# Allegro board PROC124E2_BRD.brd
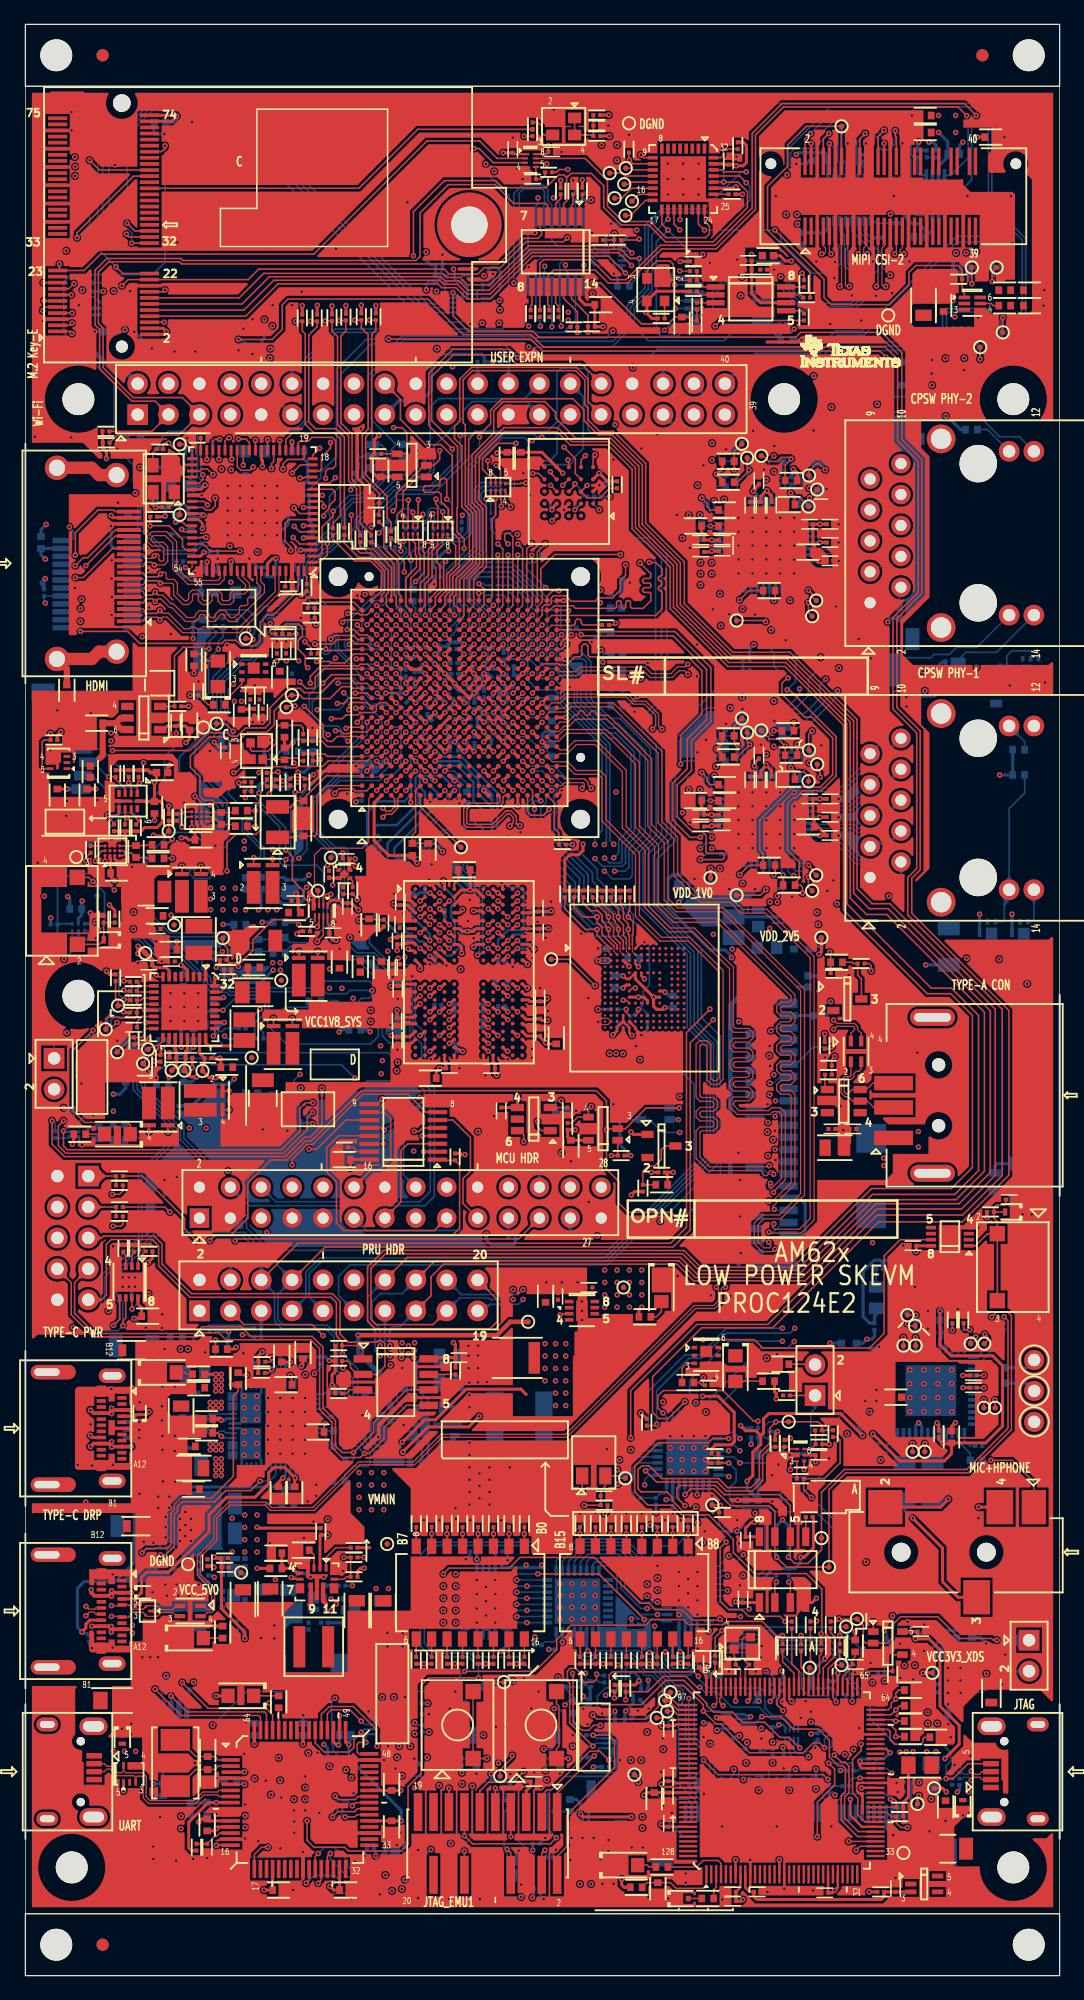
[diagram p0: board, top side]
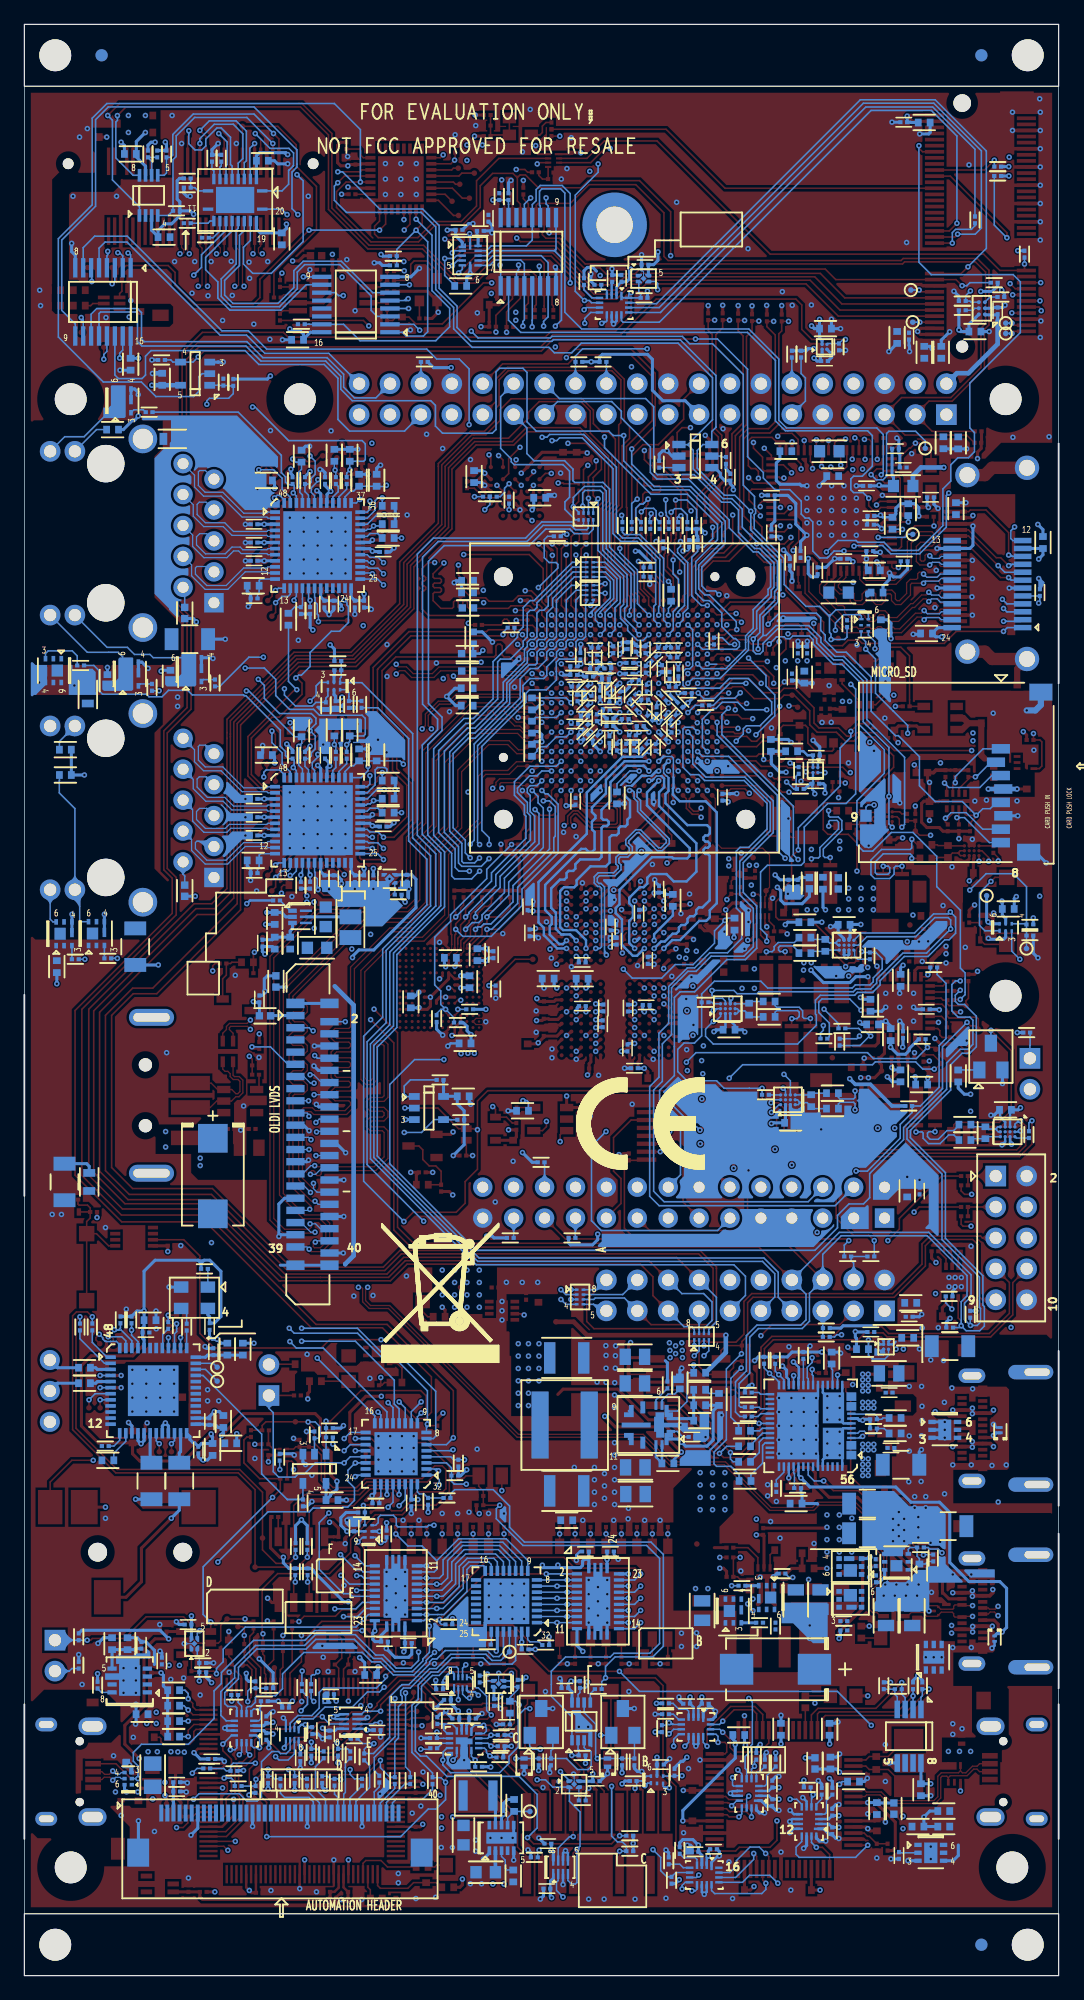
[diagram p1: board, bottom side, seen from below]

Outline 85 x 160.26 mm; copper layers: TOP, L02GND01, L03_SIG1, L04_PWR01, L05_PWR02, L06_SIG2, L07_GND02, BOTTOM. Coordinates in mm from the lower left corner of the outline.
Outline path: rectangle 0,155.18 85,160.26 ; rectangle 0,0 85,5.08 ; 0,155.18 0,5.08 85,5.08 85,155.18 0,155.18

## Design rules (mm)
net group COM_SDIO_CMD: nets COM_SDIO_CMD MMC2_CMD
net group COM_SDIO_D0: nets COM_SDIO_D0 MMC2_D0
net group COM_SDIO_D1: nets COM_SDIO_D1 MMC2_D1
net group COM_SDIO_D2: nets COM_SDIO_D2 MMC2_D2
net group COM_SDIO_D3: nets COM_SDIO_D3 MMC2_D3
net group CPSW_ETH1_D0: nets CPSW_ETH1_D0N CPSW_ETH1_D0P
net group CPSW_ETH1_D1: nets CPSW_ETH1_D1M CPSW_ETH1_D1P
net group CPSW_ETH1_D2: nets CPSW_ETH1_D2M CPSW_ETH1_D2P
net group CPSW_ETH1_D3: nets CPSW_ETH1_D3M CPSW_ETH1_D3P
net group CPSW_RGMII1_RXC: nets CPSW_RGMII1_RXC N17167245
net group CPSW_RGMII1_TXC: nets CPSW_RGMII1_TXC CPSW_RGMII_TXC_R
net group CPSW_RGMII2_RXC: nets CPSW_RGMII2_RXC N22623025
net group CPSW_RGMII2_TXC: nets CPSW_RGMII2_TXC CPSW_RGMII2_TXC_R
net group DDR_ADDRESS: nets LPDDR4_CK_N LPDDR4_CK_P
net group HDMI_PCLK: nets HDMI_PCLK SOC_VOUT0_PCLK
net group MMC2_CLK: nets MMC2_CLK SOC_MMC2_CLK
net group OSPI_CLK: nets N22727847 OSPI_CLK
net group OSPI_DQS: nets OSPI_DQS OSPI_DQS_SOC
net group SOC_OSPI_DQ0: nets OSPI_DQ0 SOC_OSPI_DQ0
net group SOC_OSPI_DQ1: nets OSPI_DQ1 SOC_OSPI_DQ1
net group SOC_OSPI_DQ2: nets OSPI_DQ2 SOC_OSPI_DQ2
net group SOC_OSPI_DQ3: nets OSPI_DQ3 SOC_OSPI_DQ3
net group SOC_OSPI_DQ4: nets OSPI_DQ4 SOC_OSPI_DQ4
net group SOC_OSPI_DQ5: nets OSPI_DQ5 SOC_OSPI_DQ5
net group SOC_OSPI_DQ6: nets OSPI_DQ6 SOC_OSPI_DQ6
net group SOC_OSPI_DQ7: nets OSPI_DQ7 SOC_OSPI_DQ7
net group SOC_USB0: nets SOC_USB0_DM SOC_USB0_DP
net group SOC_USB1: nets SOC_USB1_DM SOC_USB1_DP
net group USB0_TYPEACONN1: nets USB_TYPEACONN1_DM USB_TYPEACONN1_DP
net group USBC_CONN2: nets USBC_CONN2_DM USBC_CONN2_DP
net group XDS_USB: nets XDS_USB_DM XDS_USB_DP
net group CH_LVDS_A: nets CH1_LVDS_A0N CH1_LVDS_A0P CH1_LVDS_A1N CH1_LVDS_A1P CH1_LVDS_A2N CH1_LVDS_A2P CH1_LVDS_A3N CH1_LVDS_A3P CH1_LVDS_CLKN CH1_LVDS_CLKP CH2_LVDS_A0N CH2_LVDS_A0P CH2_LVDS_A1N CH2_LVDS_A1P CH2_LVDS_A2N CH2_LVDS_A2P CH2_LVDS_A3N CH2_LVDS_A3P CH2_LVDS_CLKN CH2_LVDS_CLKP
net group CPSW_ETH2_SIGNALS: nets CPSW_ETH2_D0N CPSW_ETH2_D0P CPSW_ETH2_D1M CPSW_ETH2_D1P CPSW_ETH2_D2M CPSW_ETH2_D2P CPSW_ETH2_D3M CPSW_ETH2_D3P
net group CSI0: nets CSI0_RXCLKN CSI0_RXCLKP CSI0_RXN0 CSI0_RXN1 CSI0_RXN2 CSI0_RXN3 CSI0_RXP0 CSI0_RXP1 CSI0_RXP2 CSI0_RXP3
net group DDR_DATA0: nets LPDDR4_DMI0 LPDDR4_DQ0 LPDDR4_DQ1 LPDDR4_DQ2 LPDDR4_DQ4 LPDDR4_DQ5 LPDDR4_DQ6 LPDDR4_DQ7 LPDDR4_DQS0_N LPDDR4_DQS0_P
net group DDR_DATA1: nets LPDDR4_DMI1 LPDDR4_DQ8 LPDDR4_DQ9 LPDDR4_DQ10 LPDDR4_DQ11 LPDDR4_DQ12 LPDDR4_DQ13 LPDDR4_DQ14 LPDDR4_DQ15 LPDDR4_DQS1_N LPDDR4_DQS1_P
net group EMMC: nets SOC_MMC0_CLK SOC_MMC0_CMD SOC_MMC0_DAT0 SOC_MMC0_DAT1 SOC_MMC0_DAT2 SOC_MMC0_DAT3 SOC_MMC0_DAT4 SOC_MMC0_DAT5 SOC_MMC0_DAT6 SOC_MMC0_DAT7
net group PWR: nets N22163762 N22221349 N22221705 N22234960 N22235133 USB_TYPEC1_EARTH USB_TYPEC2_EARTH VCC2V5_PG VCC3V3_PRU VCC3V3_XDS VCC_1V8_AUD VCC_1V8_FT4232 VCC_3V3_AUD VCC_3V3_FB VCC_3V3_FT4232 VCC_5V0_FB VCC_5V0_HDMICONN
net group VOUT: nets SOC_VOUT0_DATA0 SOC_VOUT0_DATA1 SOC_VOUT0_DATA2 SOC_VOUT0_DATA3 SOC_VOUT0_DATA4 SOC_VOUT0_DATA5 SOC_VOUT0_DATA6 SOC_VOUT0_DATA7 SOC_VOUT0_DATA8 SOC_VOUT0_DATA9 SOC_VOUT0_DATA10 SOC_VOUT0_DATA11 SOC_VOUT0_DATA12 SOC_VOUT0_DATA13 SOC_VOUT0_DATA14 SOC_VOUT0_DATA15 SOC_VOUT0_DE SOC_VOUT0_HSYNC SOC_VOUT0_VSYNC

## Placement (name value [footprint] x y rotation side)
ACC*  -  [unnamed#3]  35.67 104.94 90 top
C1  0.1uF  [CAP0402_0-75]  73.95 152.77 180 top
C2  10uF  [CAP0402_0-75]  73.95 151.37 180 top
C3  0.1uF  [CAP0201_0-5]  40.06 149.99 270 top
C4  0.1uF  [CAP0402_0-75]  79.33 151 0 top
C5  0.1uF  [CAP0201_0-5]  46.96 151.94 0 top
C6  0.01uF  [CAP0201_0-5]  57.78 149.02 270 top
C7  0.1uF  [CAP0201_0-5]  43.26 149.78 180 top
C8  1uF  [CAP0201_0-5]  59.4 140.87 0 top
C9  0.01uF  [CAP0201_0-5]  54.89 140.79 180 top
C10  0.1uF  [CAP0201_0-5]  59.4 140.11 0 top
C11  0.1uF  [CAP0201_0-5]  60.67 140.11 180 top
C12  2.2uF  [CAP0402_0-75]  82.51 138.43 0 top
C13  10uF  [CAP0805_1-5]  73.81 137.16 90 top
C14  0.1uF  [CAP0402_0-75]  75.46 137.16 90 top
C15  0.1uF  [CAP0402_0-75]  47.28 137.23 180 top
C16  10pF  [CAP0201_0-5]  55.19 135.66 270 top
C17  4.7uF  [CAP0402_0-75]  39.61 124.62 90 top
C18  0.1uF  [CAP0402_0-75]  40.73 124.62 270 top
C19  0.1uF  [CAP0402_0-75]  29.2 123.58 90 top
C25  4.7uF  [CAP0402_0-75]  48.12 109.87 90 bottom
C26  0.1uF  [CAP0201_0-5]  20.67 108.88 90 top
C27  0.1uF  [CAP0201_0-5]  21.43 108.88 90 top
C28  4.7uF  [CAP0402_0-75]  48.6 105.73 0 bottom
C31  4.7uF  [CAP0402_0-75]  48.6 104.3 0 bottom
C32  10uF  [CAP0402_0-75]  20.9 106.64 270 top
C33  0.1uF  [CAP0201_0-5]  18.48 105.08 90 top
C34  1uF  [CAP0201_0-5]  19.24 105.08 270 top
C35  0.1uF  [CAP0201_0-5]  18.81 103.77 270 top
C36  0.1uF  [CAP0201_0-5]  19.52 103.77 270 top
C37  4.7uF  [CAP0402_0-75]  17.76 103.51 270 top
C38  1uF  [CAP0201_0-5]  12.36 102.92 90 top
C39  4.7uF  [CAP0402_0-75]  5.87 102.86 180 top
C40  0.1uF  [CAP0402_0-75]  13.5 102.79 90 top
C41  18pF  [CAP0402_0-75]  21.3 102.2 90 top
C42  0.1uF  [CAP0201_0-5]  16.44 100.59 270 top
C43  18pF  [CAP0402_0-75]  21.29 100.35 270 top
C44  1uF  [CAP0201_0-5]  60.29 100.23 90 top
C45  0.01uF  [CAP0201_0-5]  59.53 98.2 270 top
C46  1uF  [CAP0201_0-5]  60.44 98.2 270 top
C47  0.1uF  [CAP0201_0-5]  61.33 98.2 270 top
C48  2.2uF  [CAP0402_0-75]  2.62 96.97 90 top
C49  0.1uF  [CAP0402_0-75]  5.08 96.97 90 top
C50  0.01uF  [CAP0201_0-5]  64.45 96.64 180 top
C51  0.1uF  [CAP0201_0-5]  66.12 96.64 0 top
C52  10uF  [CAP0402_0-75]  55.08 96.5 180 top
C53  9pF  [CAP0402_0-75]  22.86 95.99 270 top
C54  0.1uF  [CAP0402_0-75]  10.61 95.93 90 top
C55  0.1uF  [CAP0201_0-5]  55.49 95.35 180 top
C56  1uF  [CAP0201_0-5]  57.26 95.35 0 top
C57  0.1uF  [CAP0201_0-5]  66.12 95.14 0 top
C58  0.1uF  [CAP0402_0-75]  16.1 95.04 270 top
C59  0.1uF  [CAP0201_0-5]  57.26 94.44 0 top
C60  1uF  [CAP0201_0-5]  55.51 94.37 180 top
C61  10uF  [CAP0402_0-75]  64.33 94.35 180 top
C62  9pF  [CAP0402_0-75]  22.86 94.09 90 top
C63  1uF  [CAP0201_0-5]  66.12 93.64 0 top
C64  0.1uF  [CAP0402_0-75]  14.43 93.28 0 top
C65  0.1uF  [CAP0402_0-75]  9.09 92.32 270 top
C66  1uF  [CAP0201_0-5]  26.37 91.75 180 top
C67  0.1uF  [CAP0402_0-75]  7.5 90.56 0 top
C68  1uF  [CAP0201_0-5]  24.95 90.46 90 top
C69  0.1uF  [CAP0201_0-5]  6.43 86.77 270 top
C70  47uF  [CAP1206_2]  9.93 89.03 180 top
C71  0.1uF  [CAP0201_0-5]  22.15 88.29 0 top
C72  0.01uF  [CAP0201_0-5]  30.81 88.2 270 top
C73  0.1uF  [CAP0201_0-5]  26.47 87.81 270 top
C74  0.01uF  [CAP0201_0-5]  42.16 87.67 90 top
C75  4.7uF  [CAP0402_0-75]  22.12 87.31 0 top
C76  0.1uF  [CAP0402_0-75]  4.14 87.6 180 bottom
C77  0.1uF  [CAP0402_0-75]  10.83 87.04 0 top
C78  0.1uF  [CAP0201_0-5]  30.76 86.33 90 top
C79  0.1uF  [CAP0201_0-5]  10.83 85.96 0 top
C80  0.01uF  [CAP0201_0-5]  42.18 85.7 90 top
C81  0.1uF  [CAP0201_0-5]  25.27 85.64 180 top
C82  47uF  [CAP1206_2]  19.03 85 180 top
C83  0.1uF  [CAP0201_0-5]  30.55 84.98 270 top
C84  4.7uF  [CAP0402_0-75]  11.97 84.28 0 top
C85  2.2uF  [CAP0201_0-5]  12 83.3 180 top
C86  4.7uF  [CAP0402_0-75]  25.81 83.23 90 top
C87  2.2uF  [CAP0201_0-5]  10.14 82.99 180 top
C88  10uF  [CAP0402_0-75]  29.26 82.8 270 top
C89  0.1uF  [CAP0402_0-75]  18.77 82.8 0 top
C90  0.01uF  [CAP0201_0-5]  30.18 82.8 90 top
C91  0.01uF  [CAP0201_0-5]  30.78 82.79 90 top
C92  0.01uF  [CAP0201_0-5]  30.61 81.03 90 top
C93  0.01uF  [CAP0201_0-5]  42.29 80.29 270 top
C94  0.01uF  [CAP0201_0-5]  42.31 78.86 270 top
C95  0.01uF  [CAP0201_0-5]  30.54 78.36 90 top
C96  2.2uF  [CAP0201_0-5]  8.9 77.88 180 top
C97  0.01uF  [CAP0201_0-5]  42.32 77.45 270 top
C98  10uF  [CAP0402_0-75]  43.63 77.01 90 top
C99  0.01uF  [CAP0201_0-5]  30.57 76.84 90 top
C100  2.2uF  [CAP0201_0-5]  12.13 75.4 180 top
C101  2.2uF  [CAP0201_0-5]  13.45 75.4 0 top
C102  2.2uF  [CAP0201_0-5]  15 75.35 0 top
C103  0.1uF  [CAP0402_0-75]  16.55 74.61 0 top
C104  0.01uF  [CAP0201_0-5]  34.84 74.52 180 top
C105  0.01uF  [CAP0201_0-5]  38.31 74.5 0 top
C106  10uF  [CAP0402_0-75]  33.27 73.71 180 top
C107  47uF  [CAP1206_2]  19.52 72.04 270 top
C108  0.01uF  [CAP0201_0-5]  39.1 71.02 90 top
C109  0.1uF  [CAP0201_0-5]  66.28 69.54 0 top
C110  0.1uF  [CAP0201_0-5]  68.01 69.54 180 top
C111  10uF  [CAP0805_1-5]  66.52 68 0 top
C112  0.1uF  [CAP0402_0-75]  44.83 68.12 270 top
C113  0.1uF  [CAP0402_0-75]  26.22 67.02 0 top
C114  0.1uF  [CAP0201_0-5]  80.86 63.74 180 top
C115  0.1uF  [CAP0201_0-5]  72.93 59.95 180 top
C116  0.1uF  [CAP0201_0-5]  46.32 56.52 0 top
C117  10uF  [CAP0402_0-75]  42.75 55.79 90 top
C118  1uF  [CAP0201_0-5]  43.77 55.79 270 top
C119  0.1uF  [CAP0402_0-75]  10.05 54.16 0 top
C120  220pF  [CAP0402_0-75]  22.81 51.16 90 top
C121  220pF  [CAP0402_0-75]  21.07 50.88 90 top
C122  0.1uF  [CAP0201_0-5]  35.63 50.75 0 top
C123  47uF  [CAP1210_2-75]  40.43 50.73 180 top
C124  0.1uF  [CAP0201_0-5]  77.91 49.29 180 top
C125  4.7uF  [CAP0402_0-75]  21.42 48.53 180 top
C126  0.1uF  [CAP0201_0-5]  77.91 48.29 180 top
C127  0.1uF  [CAP0402_0-75]  14.25 48.28 180 top
C128  10uF  [CAP0805_1-5]  12.8 45.97 270 top
C129  10uF  [CAP0402_0-75]  14.9 45.73 0 top
C130  4.7uF  [CAP0402_0-75]  24.06 44.65 180 top
C131  10uF  [CAP0402_0-75]  14.9 44.58 0 top
C132  0.1uF  [CAP0201_0-5]  75.07 44.5 90 top
C133  10uF  [CAP0402_0-75]  76.11 44.25 90 top
C134  0.1uF  [CAP0402_0-75]  13.48 43.47 180 top
C135  0.1uF  [CAP0201_0-5]  65.22 42.75 0 top
C136  10uF  [CAP0805_1-5]  13.84 41.68 180 top
C137  0.1uF  [CAP0402_0-75]  13.82 39.95 180 top
C138  220pF  [CAP0402_0-75]  20.79 39.67 270 top
C139  220pF  [CAP0402_0-75]  22.13 39.66 270 top
C140  0.1uF  [CAP0201_0-5]  47.56 39.4 180 top
C141  0.1uF  [CAP0201_0-5]  59.18 35.76 270 top
C142  0.1uF  [CAP0402_0-75]  22.84 34.95 180 top
C143  0.1uF  [CAP0201_0-5]  14.95 33.92 90 top
C144  0.1uF  [CAP0201_0-5]  16.41 33.54 180 top
C145  22uF  [CAP0805_1-5]  20.13 30.96 270 top
C146  10uF  [CAP0805_1-5]  17.88 30.89 270 top
C147  10uF  [CAP0805_1-5]  29.42 29.98 270 top
C148  10uF  [CAP0805_1-5]  27.24 29.99 270 top
C149  0.1uF  [CAP0201_0-5]  58.98 30.91 90 top
C150  0.1uF  [CAP0201_0-5]  73.59 28.26 0 top
C151  0.1uF  [CAP0201_0-5]  55.36 25.63 270 top
C152  0.1uF  [CAP0201_0-5]  68.24 25.56 180 top
C153  12pF  [CAP0201_0-5]  58.1 25.55 0 top
C154  12pF  [CAP0201_0-5]  59.75 25.55 180 top
C155  0.1uF  [CAP0201_0-5]  52.85 20.24 90 top
C156  18pF  [CAP0402_0-75]  14.99 18.49 90 top
C157  18pF  [CAP0402_0-75]  14.99 16.44 270 top
C158  0.01uF  [CAP0201_0-5]  52.85 16.26 90 top
C159  0.1uF  [CAP0201_0-5]  41.79 15.95 0 top
C160  0.1uF  [CAP0402_0-75]  30.1 15.7 270 top
C161  1uF  [CAP0201_0-5]  52.85 14.75 270 top
C162  2.2uF  [CAP0402_0-75]  51.68 14.54 270 top
C163  4.7uF  [CAP0402_0-75]  75.62 13.87 270 top
C164  0.01uF  [CAP0201_0-5]  52.85 12.51 90 top
C165  0.1uF  [CAP0402_0-75]  14.94 12.38 90 top
C166  0.1uF  [CAP0402_0-75]  30.1 12.22 90 top
C167  0.1uF  [CAP0201_0-5]  14.95 10.55 90 top
C168  1000pF  [CAP1206_1-75]  75.81 10.42 0 top
C169  0.01uF  [CAP0201_0-5]  71.51 7.16 90 top
C170  0.1uF  [CAP0402_0-75]  20.81 7.03 180 top
C171  0.1uF  [CAP0402_0-75]  26.31 7.03 180 top
C172  0.01uF  [CAP0201_0-5]  58.12 6.88 180 top
C173  0.1uF  [CAP0201_0-5]  60.15 6.88 180 top
C174  0.01uF  [CAP0201_0-5]  65.69 6.81 180 top
C175  1uF  [CAP0201_0-5]  58.12 6.12 180 top
C176  0.1uF  [CAP0201_0-5]  12.73 152.22 180 bottom
C177  10uF  [CAP0402_0-75]  11.05 152.2 180 bottom
C178  0.1uF  [CAP0201_0-5]  46.86 144.33 90 bottom
C179  0.1uF  [CAP0201_0-5]  49.28 143.38 0 bottom
C180  0.1uF  [CAP0201_0-5]  47.52 143.3 0 bottom
C181  0.1uF  [CAP0402_0-75]  62.54 134.35 180 bottom
C182  0.1uF  [CAP0201_0-5]  33.99 140.52 180 bottom
C183  0.1uF  [CAP0201_0-5]  36.69 139.39 270 bottom
C184  0.1uF  [CAP0201_0-5]  35.93 139.39 270 bottom
C185  1uF  [CAP0201_0-5]  5.01 136.73 90 bottom
C186  2.2uF  [CAP0402_0-75]  19.16 135.26 180 bottom
C187  2.2uF  [CAP0402_0-75]  6.88 135.03 180 bottom
C188  0.1uF  [CAP0201_0-5]  12.3 134.65 90 bottom
C189  10uF  [CAP0402_0-75]  13.28 134.54 270 bottom
C190  0.1uF  [CAP0402_0-75]  11.04 133.32 270 bottom
C191  2.2uF  [CAP0402_0-75]  9.64 133.32 90 bottom
C192  1uF  [CAP0201_0-5]  19.24 132.6 180 bottom
C193  0.1uF  [CAP0402_0-75]  76.26 132.34 90 bottom
C194  0.1uF  [CAP0402_0-75]  73.67 131.11 90 bottom
C195  0.1uF  [CAP0402_0-75]  9.47 125.9 90 bottom
C196  2.2uF  [CAP0402_0-75]  8.25 125.88 270 bottom
C197  0.1uF  [CAP0201_0-5]  13.41 125.41 180 bottom
C198  10uF  [CAP0402_0-75]  22.42 125.2 0 bottom
C201  2.2uF  [CAP0201_0-5]  12.77 123.87 0 bottom
C202  10uF  [CAP0402_0-75]  18.57 123.16 0 bottom
C203  0.1uF  [CAP0402_0-75]  48.04 123.12 270 bottom
C204  0.01uF  [CAP0201_0-5]  26.99 123.06 270 bottom
C205  0.1uF  [CAP0201_0-5]  15.79 122.35 0 bottom
C206  0.1uF  [CAP0201_0-5]  23.61 121.57 180 bottom
C208  0.1uF  [CAP0201_0-5]  10.53 121.42 0 bottom
C209  0.1uF  [CAP0402_0-75]  42.65 121.37 180 bottom
C212  10uF  [CAP0402_0-75]  8.44 120.48 90 bottom
C213  0.1uF  [CAP0201_0-5]  15.43 119.89 0 bottom
C214  0.1uF  [CAP0201_0-5]  15.47 119.17 0 bottom
C215  0.1uF  [CAP0201_0-5]  23.61 118.49 90 bottom
C217  10uF  [CAP0402_0-75]  1.29 117.7 90 bottom
C219  0.1uF  [CAP0201_0-5]  15.52 117 0 bottom
C220  0.1uF  [CAP0201_0-5]  21.21 116.72 90 bottom
C221  0.1uF  [CAP0201_0-5]  17.65 116.37 0 bottom
C222  0.1uF  [CAP0201_0-5]  22.09 116.08 270 bottom
C223  2.2uF  [CAP0201_0-5]  19.8 115.38 90 bottom
C225  4.7uF  [CAP0402_0-75]  48.57 114.56 0 bottom
C226  4.7uF  [CAP0402_0-75]  48.57 113.6 0 bottom
C227  4.7uF  [CAP0402_0-75]  14.92 113.59 180 bottom
C230  0.1uF  [CAP0402_0-75]  14.61 110.86 270 bottom
C232  10uF  [CAP0402_0-75]  10.86 110.23 180 bottom
C234  1uF  [CAP0201_0-5]  35.42 109.23 90 bottom
C235  0.1uF  [CAP0201_0-5]  31.57 109.06 0 bottom
C236  0.1uF  [CAP0201_0-5]  38.11 109.05 0 bottom
C237  0.1uF  [CAP0201_0-5]  32.63 109.04 180 bottom
C238  0.1uF  [CAP0201_0-5]  34.76 109.02 90 bottom
C239  1uF  [CAP0201_0-5]  33.96 108.9 90 bottom
C240  1uF  [CAP0201_0-5]  36.59 108.89 90 bottom
C241  0.1uF  [CAP0201_0-5]  21.43 108.88 90 bottom
C242  0.1uF  [CAP0201_0-5]  20.67 108.88 90 bottom
C244  0.1uF  [CAP0201_0-5]  39.3 108.37 90 bottom
C246  1uF  [CAP0201_0-5]  31.63 108.26 180 bottom
C247  0.1uF  [CAP0201_0-5]  37.94 108.22 270 bottom
C248  0.1uF  [CAP0201_0-5]  33.27 108.13 315 bottom
C249  0.1uF  [CAP0201_0-5]  35.24 107.81 0 bottom
C252  0.1uF  [CAP0201_0-5]  39.85 107.54 0 bottom
C253  0.1uF  [CAP0201_0-5]  37.05 107.36 0 bottom
C254  0.1uF  [CAP0201_0-5]  32.59 107.35 270 bottom
C255  0.1uF  [CAP0201_0-5]  38.22 107.32 180 bottom
C256  1uF  [CAP0201_0-5]  33.94 107.29 90 bottom
C257  0.1uF  [CAP0201_0-5]  31.25 106.99 270 bottom
C258  0.1uF  [CAP0201_0-5]  35.29 106.92 180 bottom
C259  0.1uF  [CAP0201_0-5]  39.85 106.83 0 bottom
C260  1uF  [CAP0201_0-5]  31.98 106.79 270 bottom
C261  0.1uF  [CAP0201_0-5]  38.54 106.69 180 bottom
C262  0.1uF  [CAP0201_0-5]  21.91 106.65 270 bottom
C263  10uF  [CAP0402_0-75]  20.9 106.65 270 bottom
C264  0.1uF  [CAP0201_0-5]  37.25 106.54 0 bottom
C265  0.1uF  [CAP0201_0-5]  34.78 106.41 0 bottom
C266  1uF  [CAP0201_0-5]  39.74 105.85 0 bottom
C267  0.1uF  [CAP0201_0-5]  31.73 105.85 180 bottom
C268  0.1uF  [CAP0201_0-5]  33.84 105.75 90 bottom
C269  0.1uF  [CAP0201_0-5]  38.87 105.74 315 bottom
C270  0.1uF  [CAP0201_0-5]  36.5 105.77 315 bottom
C271  0.1uF  [CAP0201_0-5]  37.13 105.6 270 bottom
C272  0.1uF  [CAP0201_0-5]  30.43 105.34 180 bottom
C273  0.1uF  [CAP0201_0-5]  37.68 105.27 90 bottom
C274  0.01uF  [CAP0201_0-5]  36.05 105.19 90 bottom
C275  0.1uF  [CAP0201_0-5]  38.67 105.11 0 bottom
C277  0.1uF  [CAP0201_0-5]  39.55 104.94 90 bottom
C278  1uF  [CAP0201_0-5]  32.47 104.94 225 bottom
C279  0.1uF  [CAP0201_0-5]  34.98 105.03 315 bottom
C281  0.1uF  [CAP0201_0-5]  34.02 104.81 0 bottom
C282  0.01uF  [CAP0201_0-5]  36.64 104.54 0 bottom
C284  1uF  [CAP0201_0-5]  31.11 104.36 225 bottom
C285  0.1uF  [CAP0201_0-5]  38.87 104.14 315 bottom
C286  0.1uF  [CAP0201_0-5]  34.87 104.13 45 bottom
C287  0.1uF  [CAP0201_0-5]  37.17 104.02 0 bottom
C288  0.1uF  [CAP0201_0-5]  33.04 103.89 270 bottom
C289  0.1uF  [CAP0201_0-5]  38.97 103.41 0 bottom
C290  0.1uF  [CAP0201_0-5]  32.47 103.34 315 bottom
C291  0.1uF  [CAP0201_0-5]  31.67 103.34 315 bottom
C292  0.1uF  [CAP0201_0-5]  37.95 103.31 90 bottom
C293  0.1uF  [CAP0201_0-5]  33.59 103.3 225 bottom
C294  0.1uF  [CAP0201_0-5]  36.87 103.24 0 bottom
C295  0.1uF  [CAP0201_0-5]  35.62 103.21 0 bottom
C296  0.1uF  [CAP0201_0-5]  39.76 102.8 0 bottom
C297  0.1uF  [CAP0201_0-5]  36.87 102.63 0 bottom
C298  0.1uF  [CAP0201_0-5]  34.39 102.63 0 bottom
C299  0.1uF  [CAP0201_0-5]  38.9 102.55 315 bottom
C300  1uF  [CAP0201_0-5]  31.81 102.38 90 bottom
C301  1uF  [CAP0201_0-5]  35.02 101.86 180 bottom
C302  0.01uF  [CAP0201_0-5]  32.48 101.72 225 bottom
C303  0.1uF  [CAP0201_0-5]  38.85 101.71 315 bottom
C304  1uF  [CAP0201_0-5]  38.09 101.67 315 bottom
C305  1uF  [CAP0201_0-5]  36.92 101.51 90 bottom
C306  0.1uF  [CAP0201_0-5]  34.05 100.97 315 bottom
C307  0.1uF  [CAP0201_0-5]  36.31 100.9 270 bottom
C308  0.1uF  [CAP0201_0-5]  34.88 100.9 270 bottom
C309  0.1uF  [CAP0201_0-5]  35.54 100.89 270 bottom
C310  0.01uF  [CAP0201_0-5]  33.13 100.87 270 bottom
C311  4.7uF  [CAP0402_0-75]  23.65 101.04 90 bottom
C312  10uF  [CAP0402_0-75]  65.1 100.25 0 bottom
C313  0.1uF  [CAP0201_0-5]  60.29 100.23 90 bottom
C314  0.1uF  [CAP0201_0-5]  27.64 96.79 90 bottom
C315  0.1uF  [CAP0201_0-5]  66.12 96.64 0 bottom
C316  0.1uF  [CAP0201_0-5]  39.7 96.45 90 bottom
C317  1uF  [CAP0201_0-5]  66.12 95.14 0 bottom
C318  0.01uF  [CAP0201_0-5]  55.51 94.37 180 bottom
C319  1uF  [CAP0201_0-5]  66.12 93.64 0 bottom
C320  22pF  [CAP0201_0-5]  66.12 90.55 180 bottom
C321  1uF  [CAP0201_0-5]  53.56 90.12 270 bottom
C322  0.1uF  [CAP0201_0-5]  60.34 90.09 270 bottom
C323  1uF  [CAP0201_0-5]  59.58 90.09 270 bottom
C324  1uF  [CAP0201_0-5]  57.84 90.09 270 bottom
C325  0.1uF  [CAP0201_0-5]  57.08 90.09 270 bottom
C326  1uF  [CAP0201_0-5]  56.32 90.09 270 bottom
C327  1uF  [CAP0201_0-5]  22.2 89.72 270 bottom
C328  0.1uF  [CAP0201_0-5]  21.43 89.72 270 bottom
C329  4.7uF  [CAP0402_0-75]  19.36 89.72 270 bottom
C330  0.01uF  [CAP0201_0-5]  32.84 89.23 270 bottom
C331  0.01uF  [CAP0201_0-5]  43.64 87.79 270 bottom
C332  0.01uF  [CAP0201_0-5]  34.48 87.25 270 bottom
C333  4.7uF  [CAP0603_1]  60.23 86.96 270 bottom
C334  0.1uF  [CAP0402_0-75]  20.85 86.52 180 bottom
C335  0.1uF  [CAP0402_0-75]  17.63 86.3 0 bottom
C336  0.01uF  [CAP0201_0-5]  36.83 86.13 270 bottom
C337  0.01uF  [CAP0201_0-5]  43.49 85.64 90 bottom
C338  1000pF  [CAP1206_1-75]  75.89 84.51 270 bottom
C339  0.01uF  [CAP0201_0-5]  36.31 84.96 270 bottom
C340  120pF  [CAP0201_0-5]  65.44 84.8 90 bottom
C341  0.1uF  [CAP0402_0-75]  19.17 84.61 90 bottom
C342  22uF  [CAP0603_1]  60.94 84.42 0 bottom
C343  1uF  [CAP0201_0-5]  46.44 83.85 90 bottom
C344  0.1uF  [CAP0402_0-75]  47.77 83.85 90 bottom
C345  0.1uF  [CAP0402_0-75]  49.99 83.59 180 bottom
C346  0.01uF  [CAP0201_0-5]  33.77 83.38 90 bottom
C347  0.01uF  [CAP0201_0-5]  39.15 83.22 0 bottom
C348  4.7uF  [CAP0402_0-75]  41.95 81.89 0 bottom
C349  10uF  [CAP0402_0-75]  39.16 81.87 180 bottom
C350  4.7uF  [CAP0402_0-75]  12.99 81.75 90 bottom
C351  0.1uF  [CAP0402_0-75]  48.41 81.63 270 bottom
C352  2.2uF  [CAP0402_0-75]  53.24 79.98 90 bottom
C353  0.01uF  [CAP0201_0-5]  33.9 79.72 0 bottom
C354  4.7uF  [CAP0402_0-75]  15.46 79.69 90 bottom
C355  0.01uF  [CAP0201_0-5]  39.14 79.63 180 bottom
C356  0.01uF  [CAP0201_0-5]  37.42 79.48 90 bottom
C357  0.01uF  [CAP0201_0-5]  35.38 79.47 90 bottom
C358  0.1uF  [CAP0402_0-75]  25.44 79.38 270 bottom
C359  2.2uF  [CAP0201_0-5]  10.88 79.36 0 bottom
C360  1uF  [CAP0201_0-5]  37.47 78.17 270 bottom
C361  4.7uF  [CAP0402_0-75]  15.29 78.12 0 bottom
C362  0.1uF  [CAP0402_0-75]  27.09 77.68 180 bottom
C363  4.7uF  [CAP0402_0-75]  13.8 77.28 270 bottom
C364  2.2uF  [CAP0201_0-5]  12.79 77.28 90 bottom
C365  2.2uF  [CAP0402_0-75]  48.78 76.57 0 bottom
C366  0.1uF  [CAP0201_0-5]  35.43 76.19 90 bottom
C367  0.01uF  [CAP0201_0-5]  34.87 74.53 180 bottom
C368  0.1uF  [CAP0402_0-75]  13 73.9 270 bottom
C369  0.1uF  [CAP0402_0-75]  11.26 73.19 0 bottom
C370  0.1uF  [CAP0402_0-75]  48.93 72.22 180 bottom
C371  0.1uF  [CAP0402_0-75]  20.34 71.86 270 bottom
C372  0.1uF  [CAP0402_0-75]  4.37 71.11 0 bottom
C373  0.1uF  [CAP0402_0-75]  22.03 70.04 180 bottom
C374  0.1uF  [CAP0402_0-75]  6.02 69.23 90 bottom
C375  150uF_10V  [CAPT7343D_3-25]  69.51 65.67 270 bottom
C376  1000pF  [CAP1206_1-75]  81.7 65.19 270 bottom
C377  0.1uF  [CAP0402_0-75]  12.45 64.44 270 bottom
C378  1uF  [CAP0201_0-5]  11.43 64.44 90 bottom
C379  0.1uF  [CAP0201_0-5]  65.68 80.22 270 bottom
C380  2.2uF  [CAP0402_0-75]  12.15 55.26 180 bottom
C381  0.1uF  [CAP0201_0-5]  12.28 54.11 0 bottom
C382  10uF  [CAP0402_0-75]  74.67 53.83 180 bottom
C383  0.1uF  [CAP0201_0-5]  69.77 53.31 270 bottom
C384  1uF  [CAP0201_0-5]  15.43 52.86 0 bottom
C385  0.1uF  [CAP0201_0-5]  75.01 52.82 180 bottom
C386  2.2uF  [CAP0402_0-75]  12.4 52.38 180 bottom
C387  1000pF  [CAP1206_1-75]  8.93 51.7 0 bottom
C388  10uF  [CAP0402_0-75]  68.31 51.45 90 bottom
C389  0.1uF  [CAP0201_0-5]  69.46 51.24 90 bottom
C390  47uF  [CAP1210_2-75]  40.43 50.73 180 bottom
C391  1uF  [CAP0805_1-5]  34.82 50.83 0 bottom
C392  0.1uF  [CAP0402_0-75]  80.06 49.93 180 bottom
C393  1uF  [CAP0805_1-5]  13.93 49.46 180 bottom
C394  0.1uF  [CAP0402_0-75]  80.06 48.66 180 bottom
C395  10uF  [CAP0805_1-5]  34.82 48.64 0 bottom
C396  36pF  [CAP0402_0-75]  29.5 48.12 0 bottom
C397  0.01uF  [CAP0201_0-5]  13.93 47.89 180 bottom
C398  0.1uF  [CAP0201_0-5]  69.79 45.51 90 bottom
C399  10uF  [CAP0402_0-75]  68.64 45.51 90 bottom
C400  1uF  [CAP0201_0-5]  30.13 44.24 180 bottom
C401  0.01uF  [CAP0201_0-5]  13.78 43.34 180 bottom
C402  10uF  [CAP0402_0-75]  69.53 43.22 270 bottom
C403  0.1uF  [CAP0201_0-5]  70.7 43.16 270 bottom
C404  0.47uF  [CAP0402_0-75]  78.14 42.32 180 bottom
C405  0.1uF  [CAP0402_0-75]  32.12 42.07 180 bottom
C406  10uF  [CAP0805_1-5]  34.79 41.74 0 bottom
C407  4.7uF  [CAP1206_2]  12.95 41.96 180 bottom
C408  47uF  [CAP1206_2]  74.55 40.63 270 bottom
C409  47uF  [CAP1206_2]  72.27 40.63 270 bottom
C410  1uF  [CAP0805_1-5]  34.77 39.55 0 bottom
C411  47uF  [CAP1210_2-75]  40.43 39.81 180 bottom
C412  0.1uF  [CAP0402_0-75]  59.72 39.06 180 bottom
C413  0.01uF  [CAP0201_0-5]  53.2 38.82 90 bottom
C414  4.7uF  [CAP0402_0-75]  21.58 38.77 0 bottom
C415  0.1uF  [CAP0402_0-75]  40.43 37.4 180 bottom
C416  1000pF  [CAP1206_1-75]  9.08 36.92 0 bottom
C417  0.1uF  [CAP0201_0-5]  57.89 36.77 270 bottom
C418  0.1uF  [CAP0201_0-5]  38.89 34.83 180 bottom
C419  0.1uF  [CAP0201_0-5]  36.83 34.83 180 bottom
C420  22uF  [CAP0805_1-5]  21.6 30.88 270 bottom
C421  22uF  [CAP0805_1-5]  19.57 30.88 270 bottom
C422  10uF  [CAP0805_1-5]  29.3 29.98 270 bottom
C423  10uF  [CAP0805_1-5]  14.19 29.56 90 bottom
C424  10uF  [CAP0805_1-5]  12.03 29.56 90 bottom
C425  0.1uF  [CAP0201_0-5]  17.65 29.12 0 bottom
C426  0.1uF  [CAP0201_0-5]  71.55 28.83 180 bottom
C427  0.1uF  [CAP0201_0-5]  55.4 27.43 180 bottom
C428  0.1uF  [CAP0201_0-5]  53.44 27.32 0 bottom
C429  15pF  [CAP0201_0-5]  75.38 27.14 270 bottom
C430  0.01uF  [CAP0201_0-5]  43.85 26.8 0 bottom
C431  1uF  [CAP0201_0-5]  73.7 25.84 90 bottom
C432  0.1uF  [CAP0201_0-5]  40.58 23.61 180 bottom
C433  0.1uF  [CAP0201_0-5]  50.87 23.52 180 bottom
C434  0.1uF  [CAP0201_0-5]  59.83 23.12 180 bottom
C435  0.1uF  [CAP0201_0-5]  50.23 22.65 180 bottom
C436  0.01uF  [CAP0201_0-5]  46.41 22.44 90 bottom
C437  0.1uF  [CAP0201_0-5]  30.57 22.34 180 bottom
C438  0.1uF  [CAP0201_0-5]  29.05 22.34 0 bottom
C439  1uF  [CAP0201_0-5]  63.53 22.01 0 bottom
C440  2.2uF  [CAP0402_0-75]  75.32 21.47 0 bottom
C441  0.1uF  [CAP0201_0-5]  49.54 21.12 180 bottom
C442  0.1uF  [CAP0201_0-5]  48.17 21.12 0 bottom
C443  0.1uF  [CAP0201_0-5]  65.11 21.02 270 bottom
C444  8.2pF  [CAP0201_0-5]  45.37 20.64 0 bottom
C445  0.1uF  [CAP0402_0-75]  22.82 20.23 270 bottom
C446  0.1uF  [CAP0402_0-75]  18.82 20.23 270 bottom
C447  0.1uF  [CAP0201_0-5]  56.01 20.17 0 bottom
C448  0.1uF  [CAP0201_0-5]  61.34 20.13 90 bottom
C449  0.1uF  [CAP0201_0-5]  59.91 19.85 90 bottom
C450  4.7uF  [CAP0402_0-75]  26.29 19.76 180 bottom
C451  0.1uF  [CAP0201_0-5]  65.11 19.64 90 bottom
C452  0.1uF  [CAP0201_0-5]  62.32 17.89 90 bottom
C453  0.1uF  [CAP0201_0-5]  69.6 17.79 180 bottom
C454  0.1uF  [CAP0201_0-5]  41.72 17.55 90 bottom
C455  0.1uF  [CAP0201_0-5]  34.86 17.55 90 bottom
C456  0.1uF  [CAP0402_0-75]  18.76 17.46 270 bottom
C457  0.1uF  [CAP0201_0-5]  32.73 17.33 0 bottom
C458  0.01uF  [CAP0201_0-5]  38.01 15.97 0 bottom
C459  0.1uF  [CAP0201_0-5]  72.48 15.89 180 bottom
C460  0.1uF  [CAP0201_0-5]  23.53 15.73 270 bottom
C461  0.1uF  [CAP0402_0-75]  11.31 15.27 90 bottom
C462  0.1uF  [CAP0201_0-5]  72.48 15.12 180 bottom
C463  0.1uF  [CAP0201_0-5]  23.53 14.21 90 bottom
C464  0.1uF  [CAP0402_0-75]  14.94 13.72 90 bottom
C465  0.1uF  [CAP0402_0-75]  9.44 13.52 180 bottom
C466  0.1uF  [CAP0201_0-5]  18.61 13.42 270 bottom
C467  2.2uF  [CAP0402_0-75]  11.56 12.25 180 bottom
C468  10uF  [CAP0402_0-75]  9.44 12.25 180 bottom
C469  0.1uF  [CAP0201_0-5]  18.61 11.9 90 bottom
C470  22uF  [CAP0603_1]  48.91 11.54 270 bottom
C471  0.1uF  [CAP0201_0-5]  41.97 10.84 180 bottom
C472  0.1uF  [CAP0201_0-5]  28.36 10.39 0 bottom
C473  0.1uF  [CAP0201_0-5]  29.88 10.17 180 bottom
C474  0.01uF  [CAP0201_0-5]  13.12 9.87 90 bottom
C475  4.7uF  [CAP0603_1]  47.08 8.49 0 bottom
C476  0.1uF  [CAP0201_0-5]  42.05 7.15 180 bottom
C477  0.1uF  [CAP0402_0-75]  76.29 149.61 180 bottom
C478  0.1uF  [CAP0402_0-75]  73.52 142.78 0 bottom
C479  0.1uF  [CAP0402_0-75]  63.84 142.64 90 bottom
C480  0.1uF  [CAP0402_0-75]  65.44 149.06 0 bottom
C507  1uF  [CAP0201_0-5]  19.91 100.23 180 bottom
C531  1uF  [CAP0201_0-5]  19.96 97.89 180 bottom
C532  150uF_20V  [CAPT7343X_4-3]  23.27 25.16 0 bottom
C533  0.1uF  [CAP0201_0-5]  29.46 86.45 270 top
C534  47uF  [CAP1206_2]  15.72 36.33 180 bottom
C535  47uF  [CAP1206_2]  15.72 38.77 180 bottom
C562  22pF  [CAP0201_0-5]  66.12 113.1 180 bottom
C563  1uF  [CAP0201_0-5]  60.29 122.79 90 top
C564  0.1uF  [CAP0201_0-5]  57.08 112.65 270 bottom
C565  0.1uF  [CAP0201_0-5]  61.33 120.76 270 top
C566  10uF  [CAP0402_0-75]  64.33 116.91 180 top
C567  1uF  [CAP0201_0-5]  55.51 116.93 180 top
C568  1uF  [CAP0201_0-5]  60.44 120.76 270 top
C569  1uF  [CAP0201_0-5]  57.26 117.91 0 top
C570  0.1uF  [CAP0201_0-5]  60.34 112.65 270 bottom
C571  1000pF  [CAP1206_1-75]  71.4 109.76 180 bottom
C572  10uF  [CAP0402_0-75]  55.08 119.06 180 top
C573  1uF  [CAP0201_0-5]  66.12 116.2 0 top
C574  0.1uF  [CAP0201_0-5]  66.12 117.7 0 top
C575  0.1uF  [CAP0201_0-5]  66.12 119.2 0 bottom
C576  0.1uF  [CAP0201_0-5]  55.49 117.91 180 top
C577  0.1uF  [CAP0201_0-5]  57.26 116.99 0 top
C578  1uF  [CAP0201_0-5]  57.84 112.65 270 bottom
C579  10uF  [CAP0402_0-75]  65.1 122.8 0 bottom
C580  1uF  [CAP0201_0-5]  66.12 117.7 0 bottom
C581  0.1uF  [CAP0201_0-5]  60.29 122.79 90 bottom
C582  1uF  [CAP0201_0-5]  66.12 116.2 0 bottom
C583  1uF  [CAP0201_0-5]  59.58 112.65 270 bottom
C584  0.1uF  [CAP0201_0-5]  66.12 119.2 0 top
C585  0.01uF  [CAP0201_0-5]  55.51 116.93 180 bottom
C586  0.01uF  [CAP0201_0-5]  59.53 120.76 270 top
C587  0.01uF  [CAP0201_0-5]  64.45 119.2 180 top
C588  0.1uF  [CAP0201_0-5]  59.43 104.39 270 bottom
D1  TPD1E10B06DPYR  [DIO_DFN0402_0-5]  6.78 85.06 180 top
D2  BZX84C6V8LT1G  [SOT23-123_1-2]  67.55 80.21 0 top
D3  BZX84C6V8LT1G  [SOT23-123_1-2]  52.28 68.14 0 top
D4  TPD1E10B06DPYR  [DIO_DFN0402_0-5]  80.86 62.72 180 top
D5  TPD1E01B04DPLT  [DIO_DFN0201_0-4]  9.39 46.3 90 top
D6  TPD1E01B04DPLT  [DIO_DFN0201_0-4]  9.77 31.48 0 top
D7  ESD122DMXR  [X2SON3_ESD122DMX_30X40_0-4]  10.04 29.95 180 top
D8  TPD1E10B06DPYR  [DIO_DFN0402_0-5]  7.97 19.39 270 top
D9  TPD1E10B06DPYR  [DIO_DFN0402_0-5]  77.05 14.08 90 top
D10  TPD1E01B04DPLT  [DIO_DFN0201_0-4]  4.79 44.8 90 bottom
D11  TPD1E01B04DPLT  [DIO_DFN0201_0-4]  5.27 27.68 270 bottom
D12  TPD1E10B06DPYR  [DIO_DFN0402_0-5]  43.93 17.49 90 bottom
D13  TPD1E10B06DPYR  [DIO_DFN0402_0-5]  37.07 17.49 90 bottom
FB1  300E  [IND0603]  18.84 125.2 180 bottom
FB2  300E  [IND0603]  12.77 122.34 180 bottom
FB3  300E  [IND0603]  18.09 113.59 180 bottom
FL1  120E  [EMIFIL_BLM15A_0402_0-6]  61.02 141.25 180 top
FL3  120E  [EMIFIL_BLM15A_0402_0-6]  48.59 107.15 180 bottom
FL4  120E  [EMIFIL_BLM15A_0402_0-6]  48.61 108.58 180 bottom
FL6  120E  [EMIFIL_BLM15A_0402_0-6]  3.41 105.56 90 top
FL8  120E  [EMIFIL_BLM15A_0402_0-6]  5.34 98.88 270 top
FL9  120E  [EMIFIL_BLM15A_0402_0-6]  11.24 98.8 0 top
FL10  120E  [EMIFIL_BLM15A_0402_0-6]  27.52 82.88 90 top
FL11  120E  [EMIFIL_BLM15A_0402_0-6]  71.55 47.51 180 top
FL12  120E  [EMIFIL_BLM15A_0402_0-6]  48.55 112.33 180 bottom
FL14  120E  [EMIFIL_BLM15A_0402_0-6]  20.48 89.72 90 bottom
FL15  120E  [EMIFIL_BLM15A_0402_0-6]  18.11 89.7 270 bottom
FL16  120E  [EMIFIL_BLM15A_0402_0-6]  71.82 89.1 90 bottom
FL17  120E  [EMIFIL_BLM15A_0402_0-6]  64.32 81.65 90 bottom
FL18  120E  [EMIFIL_BLM15A_0402_0-6]  65.22 78.83 0 bottom
FL19  120E  [EMIFIL_BLM15A_0402_0-6]  20.03 17.43 90 bottom
FL20  120E  [EMIFIL_BLM15A_0402_0-6]  13.54 13.72 270 bottom
FL22  120E  [EMIFIL_BLM15A_0402_0-6]  71.82 111.91 90 bottom
J1  CON_PMC_2X20_F  [CON_PMC2X20_QSH-020-01-D-DP-A_S_S_S_3-4]  71.33 146.14 0 top
J2  CON_MINIPCIE_75_F  [CON_MINIPCI75_2199119-4_S_R_S_3-2_2230]  6.49 143.79 90 top
J3  HDR_2X20  [HDR_2X20_PEC20DAAN_S_T_8-6]  9.23 128.2 0 top
J5  CON_HDMI_1X19_F  [CON_19X1_10029449-001RLF_S_R_S_6-3]  3.57 115.99 270 top
J7  CON_RJ45-14_LPJG16314A4NL  [CON_RJ45-14_LPJG16314A4NL_S_R_T_13-6]  69.42 90.19 90 top
J8  HDR_1X2  [HDR_1X2_90120-0122_S_T_5-6]  2.36 75.34 90 top
J9  CON_USB-A_4_F  [CON_USBA4_629104151_S_R_S_7-4]  78.01 72.3 90 top
J10  HDR_2X14  [HDR_14X2_100_S_T]  14.31 62.22 180 top
J11  HDR_2X10  [HDR_2X10_PREC010DAAN_S_T_8-4]  14.31 54.6 0 top
J12  HDR_1X2  [HDR_1X2_90120-0122_S_T_5-6]  64.9 47.65 270 top
J13  CON_USB-C_24_F  [CON_USBC24_2012670_S_R_S_3-9]  3.88 44.95 270 top
J14  CON_AUDIOJACK4_SJ-43514-SMT  [CON_AV4_SJ-43514-SMT_S_R_S_5-1]  76.49 34.78 90 top
J15  CON_USB-C_24_F  [CON_USBC24_2012670_S_R_S_3-9]  3.88 29.95 270 top
J16  HDR_1X2  [HDR_1X2_90120-0122_S_T_5-6]  82.49 27.55 90 top
J17  CON_MUSB-B_5_F  [CON_MUSBB5_629105150521_S_R_S_2-7]  2.7 16.75 270 top
J18  CON_MUSB-B_5_F  [CON_MUSBB5_629105150521_S_R_S_2-7]  82.3 16.75 90 top
J19  HDR_2X10  [HDR_2X10_FTR-110-51-D-06_S_S_8-7]  37.99 10.86 180 top
J21  CON_SDCARD9_MEM2051-00-195-00-A  [CON_SD9_MEM2051-00-195-00_S_R_S_2-1]  8.41 98.82 90 bottom
J22  CON_FLEX_1X40_FFC2A32  [CON_FLEX1X40_FFC2A32-40-T_S_S_S_4-3]  61.32 69.1 270 bottom
J23  HDR_2X5  [HDR_2X5_PEC05DAAN_S_T_8-6]  5.17 65.67 270 bottom
J24  CON_FLEX_40X1_FH12A-40S-0.5SH  [CON_FLEX40X1_FH12A_S_R_S]  64 9.78 180 bottom
J27  CON_RJ45-14_LPJG16314A4NL  [CON_RJ45-14_LPJG16314A4NL_S_R_T_13-6]  69.42 112.75 90 top
L1  0.47uH  [IND1008_1-2]  14.26 85.1 90 top
L2  0.47uH  [IND0806_1-2]  18.68 80.76 0 top
L3  0.47uH  [IND0806_1-2]  17.99 77.66 270 top
L4  90E  [IND4_DLW21H_90X60_SMD_1-4]  68.27 75.9 270 top
L5  90E  [IND4_DLW21H_90X60_SMD_1-4]  13.54 29.95 180 top
L6  1.5uH  [IND_XFL4020_170X170_SMD_2-1]  23.7 27.01 180 top
L8  0.47uH  [IND0806_1-2]  58.2 86.11 270 bottom
L9  4.7uH  [IND_XAL6060_260X270_SMD_6-1]  40.6 45.22 0 bottom
L10  10uH  [IND_1277AS-H_130X110_SMD_1-2]  47.71 14.79 0 bottom
LD3  150080VS75000  [LED_150080VS75000_80X50_SMD_0-8]  15.81 106.92 90 top
LD5  150080VS75000  [LED_150080VS75000_80X50_SMD_0-8]  7.57 69.11 180 top
LD6  150080VS75000  [LED_150080VS75000_80X50_SMD_0-8]  52.27 56.41 270 top
LD7  150080VS75000  [LED_150080VS75000_80X50_SMD_0-8]  58.35 49.85 270 top
LD8  150080VS75000  [LED_150080VS75000_80X50_SMD_0-8]  11.35 49.54 0 top
LD9  150080VS75000  [LED_150080VS75000_80X50_SMD_0-8]  13.57 27.73 0 top
LD10  150080VS75000  [LED_150080VS75000_80X50_SMD_0-8]  17.71 22.98 180 top
LD11  150080VS75000  [LED_150080VS75000_80X50_SMD_0-8]  49.27 9.08 0 top
LD12  150040RS73220  [LED_150040GS73220_40X20_SMD_0-4]  53.97 6.33 0 top
NOREF  -  []  0 0 90 top
NOREF#2  -  []  85 155.18 0 top
NOREF#3  -  [unnamed#2]  62.36 129.47 270 top
NOREF#4  -  []  283.79 3.07 0 top
NOREF#5  -  [unnamed#2]  4.36 80.47 270 top
NOREF#6  -  [unnamed#2]  82.46 157.72 90 top
NOREF#7  -  [unnamed#2]  4.36 129.47 270 top
NOREF#8  -  []  -361.93 25.83 0 top
NOREF#9  -  []  85 5.08 0 top
NOREF#10  -  [unnamed#2]  6.35 157.72 0 top
NOREF#11  -  [unnamed#2]  2.54 157.72 270 top
NOREF#12  -  [unnamed#2]  81.19 129.47 270 top
NOREF#13  -  []  2.96 34.71 0 top
NOREF#14  -  [unnamed#2]  2.54 2.54 270 top
NOREF#15  -  [unnamed#2]  81.19 8.89 270 top
NOREF#16  -  []  0 160.26 0 top
NOREF#17  -  [unnamed#2]  82.46 2.54 90 top
NOREF#18  -  []  0.04 -82.76 0 top
NOREF#19  -  [unnamed#2]  6.35 2.54 0 top
NOREF#20  -  []  -324.66 219.96 0 top
NOREF#21  -  []  -290.23 -122.94 0 top
NOREF#22  -  [unnamed#2]  3.81 8.89 270 top
NOREF#23  -  [unnamed#2]  78.65 157.72 180 top
NOREF#24  -  [unnamed#2]  78.65 157.72 0 bottom
NOREF#25  -  [unnamed#2]  6.35 2.54 180 bottom
NOREF#26  -  [unnamed#2]  6.35 157.72 180 bottom
Q1  CSD16301Q2  [WSON6_CSD13202Q2_80X80_0-8]  18.77 107.07 0 top
Q3  CSD16301Q2  [WSON6_CSD13202Q2_80X80_0-8]  55.96 50.94 0 top
Q4  IRLML6401  [TO_SOT23-123]  46.71 42.14 0 top
Q5  CSD16301Q2  [WSON6_CSD13202Q2_80X80_0-8]  82.61 107.18 270 bottom
Q6  CSD16301Q2  [WSON6_CSD13202Q2_80X80_0-8]  79.07 85.58 90 bottom
Q7  CSD16301Q2  [WSON6_CSD13202Q2_80X80_0-8]  81.74 85.57 90 bottom
Q8  BC817  [TO_SOT23-123]  5.57 75.48 180 bottom
Q9  CSD16301Q2  [WSON6_CSD13202Q2_80X80_0-8]  13.33 33.99 0 bottom
Q10  CSD25310Q2  [SON6_CSD17313Q2_80X80]  17.12 33.6 90 bottom
Q11  CSD25310Q2  [SON6_CSD17313Q2_80X80]  17.12 30.91 270 bottom
Q12  IRLML6401  [TO_SOT23-123]  42.52 20.84 180 bottom
Q13  IRLML6401  [TO_SOT23-123]  35.81 20.84 180 bottom
Q14  CSD16301Q2  [WSON6_CSD13202Q2_80X80_0-8]  26.73 29.95 90 bottom
Q15  CSD16301Q2  [WSON6_CSD13202Q2_80X80_0-8]  23.99 31.05 270 bottom
Q19  CSD16301Q2  [WSON6_CSD13202Q2_80X80_0-8]  76.89 129.34 90 bottom
Q20  CSD16301Q2  [WSON6_CSD13202Q2_80X80_0-8]  76.27 106.91 90 bottom
Q21  CSD16301Q2  [WSON6_CSD13202Q2_80X80_0-8]  71.09 107.26 90 bottom
R1  22E_1%  [RES0201_0-5]  41.68 151.92 270 top
R2  0E  [RES0201_0-5]  41.68 151.36 90 top
R3  10K  [RES0201_0-5]  58.54 150.29 90 top
R4  10K  [RES0201_0-5]  49.6 150.01 90 top
R5  10K  [RES0201_0-5]  41.68 147.55 0 top
R6  10K  [RES0201_0-5]  43.99 146.57 270 top
R7  10K  [RES0201_0-5]  45.01 146.57 90 top
R8  10K  [RES0201_0-5]  45.77 146.57 270 top
R9  10K  [RES0201_0-5]  58.07 146.3 0 top
R10  8.2K_1%  [RES0201_0-5]  48.67 142.54 0 top
R11  10K  [RES0201_0-5]  47.2 142.54 0 top
R12  0E  [RES0201_0-5]  54.9 139.99 0 top
R13  10K  [RES0201_0-5]  76.7 139.33 180 top
R14  22E_1%  [RES0201_0-5]  54.9 139.23 0 top
R15  22E_1%  [RES0201_0-5]  63.99 138.97 90 top
R16  0E  [RES0402_0-5]  80.48 138.43 0 top
R17  10K  [RES0201_0-5]  54.9 138.33 180 top
R18  22E_1%  [RES0201_0-5]  64.21 137.82 0 top
R19  0E  [RES0402_0-5]  80.48 137.16 0 top
R20  1K_1%  [RES0402_0-5]  82.51 137.16 0 top
R21  22E_1%  [RES0201_0-5]  55.19 137.11 270 top
R22  10K  [RES0201_0-5]  41.52 136.5 90 top
R23  10K  [RES0201_0-5]  42.29 136.5 90 top
R24  10K  [RES0201_0-5]  43.05 136.5 90 top
R25  10K  [RES0201_0-5]  43.81 136.5 90 top
R26  22E_1%  [RES0201_0-5]  63.99 136.22 270 top
R27  10K_1%  [RES0201_0-5]  52.25 136.1 180 top
R28  49.9E_1%  [RES0402_0-5]  53.96 135.73 90 top
R29  4.7K  [RES0201_0-5]  46.52 135.43 180 top
R30  4.7K  [RES0201_0-5]  45.09 135.41 0 top
R31  4.7K  [RES0201_0-5]  6.62 126.83 0 top
R32  0E  [RES0201_0-5]  14.13 126.28 0 top
R33  4.7K  [RES0201_0-5]  6.64 125.89 0 top
R34  0E  [RES0201_0-5]  11.04 125.36 0 top
R35  10K  [RES0201_0-5]  28.96 124.99 180 top
R37  10K  [RES0201_0-5]  48.63 122.44 90 top
R39  10K_1%  [RES0201_0-5]  11.52 120.6 180 top
R40  0E  [RES0201_0-5]  29.06 119.68 90 top
R41  10K  [RES0201_0-5]  10.55 119.82 180 top
R43  0E  [RES0201_0-5]  47.68 110.93 0 top
R47  0E  [RES0201_0-5]  21.63 114.08 0 top
R48  4.7K  [RES0201_0-5]  23.13 114 90 top
R49  0E  [RES0201_0-5]  23.48 112.32 180 top
R51  49.9K_1%  [RES0201_0-5]  23.5 111.5 180 top
R52  22E_1%  [RES0201_0-5]  20.84 110.19 0 top
R53  0E  [RES0201_0-5]  21.4 110.19 180 top
R55  0E  [RES0201_0-5]  23.74 108.57 0 top
R56  220E  [RES0402_0-5]  13.86 108.06 270 top
R59  10K  [RES0201_0-5]  14.23 105.46 270 top
R60  0E  [RES0402_0-5]  15.94 104.38 0 top
R61  10K  [RES0201_0-5]  12.53 104.25 0 top
R63  0E  [RES0402_0-5]  62.67 102.25 180 top
R64  2.49K_1%  [RES0402_0-5]  57.77 101.82 180 top
R65  0E  [RES0201_0-5]  22.84 101.68 270 top
R66  0E  [RES0201_0-5]  23.6 101.68 270 top
R67  10K  [RES0201_0-5]  2.35 101.48 0 top
R68  2.49K_1%  [RES0402_0-5]  62.94 100.24 0 top
R69  2.49K_1%  [RES0402_0-5]  57.77 100.09 180 top
R70  0E  [RES0201_0-5]  22.86 100.05 90 top
R71  0E  [RES0201_0-5]  23.62 100.05 90 top
R73  10K  [RES0201_0-5]  9.3 98.73 90 top
R74  10K  [RES0201_0-5]  8.49 98.72 90 top
R75  10K  [RES0201_0-5]  7.42 98.72 90 top
R76  0E  [RES0201_0-5]  19.85 98.51 270 top
R77  2.49K_1%  [RES0402_0-5]  62.76 98.26 0 top
R78  0E  [RES0201_0-5]  18.3 98.03 180 top
R79  0E  [RES0201_0-5]  19.85 97.95 90 top
R80  10K  [RES0201_0-5]  20.56 97.95 270 top
R81  2.49K_1%  [RES0402_0-5]  57.45 97.81 180 top
R82  0E  [RES0201_0-5]  18.3 97.27 0 top
R83  2.49K_1%  [RES0402_0-5]  57.45 96.51 180 top
R84  10E_1%  [RES0402_0-5]  17.75 95.68 0 top
R85  0E  [RES0201_0-5]  12.46 95.13 270 top
R86  10K_1%  [RES0201_0-5]  11.78 95.13 90 top
R87  10E_1%  [RES0402_0-5]  17.75 94.41 0 top
R88  10K  [RES0201_0-5]  7.28 94.27 270 top
R89  10K  [RES0201_0-5]  8.2 94.27 270 top
R90  10K  [RES0201_0-5]  9.11 94.27 270 top
R91  22E_1%  [RES0201_0-5]  44.13 92.9 180 top
R92  10E_1%  [RES0402_0-5]  10.91 92.87 0 top
R93  2.2K  [RES0402_0-5]  31.8 92.5 270 top
R94  2.2K  [RES0402_0-5]  33.09 92.5 90 top
R95  0E  [RES0201_0-5]  5.37 92.49 270 top
R96  10E_1%  [RES0402_0-5]  10.91 91.75 0 top
R98  0E  [RES0402_0-5]  61.12 91.19 0 top
R100  240E_1%  [RES0402_0-5]  36.07 90.83 180 top
R101  0.01E_1%  [RES_KRL3216T4_1206-4_0-7]  19.54 89.7 0 top
R102  0E  [RES0402_0-5]  62.77 89.56 180 top
R103  0E  [RES0201_0-5]  26.9 89.12 90 top
R104  10K  [RES0201_0-5]  26.13 89.12 90 top
R105  10K  [RES0201_0-5]  7.35 86.77 270 top
R106  0.01E_1%  [RES_KRL3216T4_1206-4_0-7]  13.64 88.97 0 top
R107  49.9K_1%  [RES0201_0-5]  44.33 88.84 270 top
R108  49.9K_1%  [RES0201_0-5]  45.09 88.84 270 top
R109  49.9K_1%  [RES0201_0-5]  45.86 88.84 270 top
R110  49.9K_1%  [RES0201_0-5]  46.62 88.84 270 top
R111  49.9K_1%  [RES0201_0-5]  47.38 88.84 270 top
R112  49.9K_1%  [RES0201_0-5]  48.14 88.84 270 top
R113  49.9K_1%  [RES0201_0-5]  48.9 88.84 270 top
R114  49.9K_1%  [RES0201_0-5]  49.67 88.84 270 top
R115  9.76K_0.1%  [RES0402_0-5]  28.24 86.31 270 top
R116  10K  [RES0201_0-5]  23.1 85.77 0 top
R117  10K  [RES0201_0-5]  16.27 83.42 180 top
R118  16.5K_1%  [RES0402_0-5]  66.66 83.23 0 top
R119  3.4K_1%  [RES0201_0-5]  68.68 83.13 0 top
R120  10K_1%  [RES0201_0-5]  66.45 82.33 0 top
R121  0.01E_1%  [RES_KRL3216T4_1206-4_0-7]  23.25 82.09 0 top
R122  10K  [RES0201_0-5]  7.41 81.96 90 top
R123  0E  [RES0201_0-5]  8.87 81.64 0 top
R124  10K_1%  [RES0201_0-5]  46.26 81.03 270 bottom
R125  0E  [RES0201_0-5]  8.87 80.88 0 top
R126  0E  [RES0201_0-5]  8.87 80.11 0 top
R127  10K  [RES0201_0-5]  8.87 79.1 180 top
R128  10K  [RES0201_0-5]  8.93 76.77 270 top
R129  0.01E_1%  [RES_KRL3216T4_1206-4_0-7]  21.17 76.49 0 top
R130  10K  [RES0201_0-5]  11.11 75.35 270 top
R131  10K  [RES0201_0-5]  65.99 74.76 180 top
R132  0E  [RES0201_0-5]  65.99 73.99 180 top
R134  0.01E_1%  [RES_KRL3216T4_1206-4_0-7]  14.7 71.89 270 top
R136  0.01E_1%  [RES_KRL3216T4_1206-4_0-7]  10.93 71.34 180 top
R137  10K  [RES0201_0-5]  44.55 71.02 270 top
R138  49.9K_1%  [RES0201_0-5]  44.56 69.75 90 top
R139  220E  [RES0402_0-5]  4.47 69.11 180 top
R140  10K  [RES0201_0-5]  26.22 68.04 180 top
R141  10K  [RES0201_0-5]  48.96 67.35 0 top
R142  10K  [RES0201_0-5]  35.32 67.24 270 top
R143  10K_1%  [RES0201_0-5]  52.29 65.97 180 top
R144  0E  [RES0201_0-5]  7.73 65.67 180 top
R145  16.5K_1%  [RES0402_0-5]  52.29 64.96 180 top
R146  0E  [RES0201_0-5]  7.73 64.91 180 top
R147  3.4K_1%  [RES0201_0-5]  50.75 64.68 270 top
R148  0E  [RES0201_0-5]  7.73 63.13 180 top
R149  10K  [RES0201_0-5]  79.31 62.72 0 top
R150  0E  [RES0201_0-5]  7.73 62.37 180 top
R151  10K  [RES0201_0-5]  65.69 76.39 270 top
R152  10K  [RES0201_0-5]  8.03 59.73 90 top
R153  10K  [RES0201_0-5]  8.92 59.73 90 top
R154  10K  [RES0201_0-5]  10.16 59.49 180 top
R155  220E  [RES0402_0-5]  50.91 54.11 180 top
R156  10K  [RES0201_0-5]  76.19 53.86 90 top
R157  10K  [RES0201_0-5]  77.1 53.86 90 top
R158  10K  [RES0201_0-5]  25.75 51.75 0 top
R159  0E  [RES0603_0-75]  8.72 51.37 0 top
R160  10K  [RES0201_0-5]  25.75 50.48 0 top
R161  10K  [RES0201_0-5]  19.44 50.42 0 top
R162  1K_1%  [RES0402_0-5]  62.25 50.22 0 top
R163  10K  [RES0201_0-5]  35.35 49.66 270 top
R164  10K  [RES0201_0-5]  19.41 49.49 0 top
R165  1K_1%  [RES0402_0-5]  14.23 49.39 180 top
R166  0E  [RES0402_0-5]  17.49 49.03 90 top
R167  220E  [RES0402_0-5]  61.07 48.82 0 top
R168  0E  [RES0402_0-5]  54.46 48.71 180 top
R170  10K  [RES0201_0-5]  56.13 48.49 180 top
R171  10K  [RES0201_0-5]  25.75 47.81 0 top
R172  10K  [RES0201_0-5]  62.56 47.65 180 top
R173  10K  [RES0201_0-5]  51.06 45.45 90 top
R174  0E  [RES0201_0-5]  65.17 44.78 180 top
R175  0E  [RES0201_0-5]  66.38 44.52 90 top
R176  10K  [RES0201_0-5]  61.62 43.72 90 top
R177  10K  [RES0201_0-5]  62.38 43.72 90 top
R178  10K  [RES0201_0-5]  65.22 43.64 0 top
R179  10K  [RES0201_0-5]  56.67 42.87 180 top
R180  10K  [RES0201_0-5]  56.67 42.11 0 top
R181  0E  [RES0201_0-5]  63.68 40.81 180 top
R182  10K  [RES0201_0-5]  47.56 38.64 180 top
R183  4.7K  [RES0201_0-5]  57.29 38.04 0 top
R184  100K  [RES0201_0-5]  32.12 37.12 90 top
R185  100K  [RES0201_0-5]  33.39 37.12 90 top
R186  100K  [RES0201_0-5]  34.66 37.12 90 top
R187  100K  [RES0201_0-5]  35.93 37.12 90 top
R188  100K  [RES0201_0-5]  37.2 37.12 90 top
R189  100K  [RES0201_0-5]  38.47 37.12 90 top
R190  100K  [RES0201_0-5]  39.74 37.12 90 top
R191  100K  [RES0201_0-5]  41.01 37.12 90 top
R192  100K  [RES0201_0-5]  45.58 37.12 90 top
R193  100K  [RES0201_0-5]  46.85 37.12 90 top
R194  100K  [RES0201_0-5]  48.12 37.12 90 top
R195  100K  [RES0201_0-5]  49.39 37.12 90 top
R196  100K  [RES0201_0-5]  50.66 37.12 90 top
R197  100K  [RES0201_0-5]  51.93 37.12 90 top
R198  100K  [RES0201_0-5]  53.2 37.12 90 top
R199  100K  [RES0201_0-5]  54.47 37.12 90 top
R200  10K  [RES0201_0-5]  64.41 37.67 0 top
R201  0E  [RES0603_0-75]  9.08 36.92 0 top
R202  10K_1%  [RES0201_0-5]  24.28 36.48 90 top
R203  10K_1%  [RES0201_0-5]  27.01 35.15 180 top
R206  130K_1%  [RES0402_0-5]  20.59 34.69 180 top
R207  0E  [RES0201_0-5]  27.01 34.35 180 top
R208  10K_1%  [RES0201_0-5]  16.36 34.29 180 top
R209  680K_1%  [RES0402_0-5]  20.59 33.45 0 top
R210  10K  [RES0201_0-5]  27.01 32.75 0 top
R211  0E  [RES0201_0-5]  62.99 28.8 90 top
R212  0E  [RES0201_0-5]  64.51 28.8 90 top
R213  0E  [RES0201_0-5]  66.16 28.8 90 top
R214  1K_1%  [RES0402_0-5]  16.21 28.22 270 top
R215  49.9E_1%  [RES0402_0-5]  68.2 27.08 90 top
R216  0E  [RES0201_0-5]  65.4 27.03 90 top
R217  0E  [RES0201_0-5]  62.23 26.97 90 top
R218  0E  [RES0201_0-5]  63.75 26.95 90 top
R219  0E  [RES0201_0-5]  66.93 26.95 90 top
R220  0E  [RES0201_0-5]  56.68 25.99 90 top
R221  1.1K_1%  [RES0201_0-5]  32.12 25.89 270 top
R222  1.1K_1%  [RES0201_0-5]  33.39 25.89 270 top
R223  1.1K_1%  [RES0201_0-5]  34.66 25.89 270 top
R224  1.1K_1%  [RES0201_0-5]  35.93 25.89 270 top
R225  1.1K_1%  [RES0201_0-5]  37.2 25.89 270 top
R226  1.1K_1%  [RES0201_0-5]  38.47 25.89 270 top
R227  1.1K_1%  [RES0201_0-5]  39.74 25.89 270 top
R228  1.1K_1%  [RES0201_0-5]  41.01 25.89 270 top
R229  1.1K_1%  [RES0201_0-5]  45.58 25.89 270 top
R230  1.1K_1%  [RES0201_0-5]  46.85 25.89 270 top
R231  1.1K_1%  [RES0201_0-5]  48.12 25.89 270 top
R232  1.1K_1%  [RES0201_0-5]  49.39 25.89 270 top
R233  1.1K_1%  [RES0201_0-5]  50.66 25.89 270 top
R234  1.1K_1%  [RES0201_0-5]  51.93 25.89 270 top
R235  1.1K_1%  [RES0201_0-5]  53.2 25.89 270 top
R236  1.1K_1%  [RES0201_0-5]  54.47 25.89 270 top
R237  10K  [RES0201_0-5]  71.27 24.73 90 top
R238  10K  [RES0201_0-5]  48.42 23.59 270 top
R239  10K  [RES0201_0-5]  49.34 23.59 270 top
R240  1K_1%  [RES0402_0-5]  72.73 23.44 180 top
R241  0E  [RES0603_0-75]  79.39 23.17 270 top
R242  0E  [RES0805_0-75]  7.12 22.6 180 top
R243  220E  [RES0402_0-5]  20.82 22.49 90 top
R244  1K_1%  [RES0402_0-5]  72.73 22.17 180 top
R245  1K_1%  [RES0402_0-5]  72.73 20.9 180 top
R246  1K_1%  [RES0402_0-5]  72.73 19.63 180 top
R247  4.87K_1%  [RES0402_0-5]  74.82 19.58 0 top
R248  0E  [RES0805_0-75]  73.52 17.29 0 top
R249  4.7K  [RES0201_0-5]  71.84 13.83 180 top
R250  4.7K  [RES0201_0-5]  71.84 13.07 180 top
R251  10K_1%  [RES0201_0-5]  14.06 10.55 270 top
R252  220E  [RES0402_0-5]  52.31 8.93 180 top
R253  30K  [RES0402_0-5]  50.2 7.26 0 top
R254  20K_1%  [RES0402_0-5]  51.98 7.15 270 top
R255  4.7K  [RES0201_0-5]  70.3 6.88 0 top
R256  220E  [RES0402_0-5]  56.08 6.33 180 top
R257  10K  [RES0201_0-5]  5 148.57 180 bottom
R258  10K  [RES0201_0-5]  5.01 147.8 180 bottom
R259  10K  [RES0201_0-5]  45.97 146.11 90 bottom
R260  10K  [RES0201_0-5]  45.21 146.11 270 bottom
R261  33E  [RES0201_0-5]  6.88 144.2 90 bottom
R262  10K  [RES0201_0-5]  2.81 141.39 90 bottom
R263  10K  [RES0201_0-5]  54.67 141.22 0 bottom
R264  10K  [RES0201_0-5]  54.67 140.46 180 bottom
R272  49.9K_1%  [RES0201_0-5]  28.8 120.95 180 top
R273  0E  [RES0201_0-5]  28.42 118.01 270 top
R274  0E  [RES0201_0-5]  30.05 118.34 270 top
R275  0E  [RES0201_0-5]  26.21 118.62 270 top
R276  0E  [RES0201_0-5]  27.51 118.01 270 top
R277  0E  [RES0201_0-5]  25.27 118.59 270 top
R278  10K  [RES0201_0-5]  39.01 139.13 90 bottom
R279  10K  [RES0201_0-5]  5.29 139.04 180 bottom
R280  10K  [RES0201_0-5]  37.87 138.87 180 bottom
R281  100K_1%  [RES0402_0-5]  49.14 138.77 0 bottom
R282  10K_1%  [RES0201_0-5]  27.61 136.25 90 top
R283  10K_1%  [RES0201_0-5]  26.34 136.22 90 top
R284  10K_1%  [RES0201_0-5]  28.8 136.25 90 top
R285  10K_1%  [RES0201_0-5]  23.98 136.14 90 top
R286  10K_1%  [RES0201_0-5]  25.2 136.17 90 top
R287  10K_1%  [RES0201_0-5]  22.76 136.14 90 top
R288  4.7K  [RES0201_0-5]  4.75 137.86 180 bottom
R289  10K  [RES0201_0-5]  34.07 137.79 180 bottom
R290  100K  [RES0201_0-5]  7.92 137.53 180 bottom
R291  0E  [RES0201_0-5]  7.92 136.77 180 bottom
R292  10K  [RES0201_0-5]  62.23 135.63 180 bottom
R293  100K  [RES0201_0-5]  18.05 133.77 90 bottom
R294  10K  [RES0201_0-5]  21.93 133.17 270 bottom
R295  10K  [RES0201_0-5]  21.16 133.17 270 bottom
R296  10K  [RES0201_0-5]  73.72 132.69 180 bottom
R297  10K  [RES0201_0-5]  52.13 132.53 0 bottom
R298  10K  [RES0201_0-5]  39.43 132.53 0 bottom
R299  10K  [RES0201_0-5]  37.45 132.53 180 bottom
R300  10K  [RES0201_0-5]  68.64 130.87 270 bottom
R301  10K  [RES0201_0-5]  67.83 130.84 90 bottom
R302  10K  [RES0201_0-5]  27.34 124.44 270 bottom
R303  10K  [RES0201_0-5]  32.83 124.13 90 bottom
R304  10K  [RES0201_0-5]  33.83 115.66 180 bottom
R305  1K_1%  [RES0201_0-5]  33.83 114.9 180 bottom
R307  0E  [RES0201_0-5]  47.02 121.47 0 bottom
R308  22E_1%  [RES0201_0-5]  46.46 121.47 0 bottom
R309  100K  [RES0201_0-5]  45.16 121.18 90 bottom
R310  2.2K  [RES0402_0-5]  12.36 120.4 270 bottom
R316  0E  [RES0402_0-5]  31.85 113.37 270 bottom
R317  2.2K  [RES0402_0-5]  13.65 119.28 270 bottom
R318  0E  [RES0201_0-5]  35.85 119.1 270 bottom
R319  10K  [RES0201_0-5]  35.09 119.1 270 bottom
R320  10K  [RES0201_0-5]  34.32 119.1 270 bottom
R321  10K  [RES0201_0-5]  33.56 119.1 270 bottom
R322  10K  [RES0201_0-5]  32.8 119.1 270 bottom
R323  10K  [RES0201_0-5]  32.04 119.1 270 bottom
R324  10K  [RES0201_0-5]  31.28 119.1 270 bottom
R325  10K  [RES0201_0-5]  30.51 119.1 270 bottom
R326  10K  [RES0201_0-5]  29.75 119.1 270 bottom
R329  0E  [RES0201_0-5]  41.2 118.21 180 bottom
R332  10K  [RES0201_0-5]  30.37 117.61 90 bottom
R333  10K_1%  [RES0201_0-5]  29.66 117.6 90 bottom
R334  0E  [RES0201_0-5]  32.49 117.51 270 bottom
R338  10K  [RES0201_0-5]  12.7 116.16 180 bottom
R339  4.3K_1%  [RES0402_0-5]  15.15 115.42 0 bottom
R342  0E  [RES0201_0-5]  1.54 113.59 90 bottom
R345  10K  [RES0201_0-5]  17.39 111.04 90 bottom
R346  0E  [RES0201_0-5]  45 110.7 0 bottom
R348  0E  [RES0201_0-5]  28.32 109.61 270 bottom
R352  0E  [RES0201_0-5]  80.38 107.6 0 bottom
R354  0E  [RES0603_0-75]  79.78 105.22 90 bottom
R356  499E_1%  [RES0402_0-5]  43.28 104.45 90 bottom
R359  22E_1%  [RES0201_0-5]  29 104.33 0 bottom
R361  499E_1%  [RES0402_0-5]  43.28 102.54 270 bottom
R362  2.49K_1%  [RES0402_0-5]  59.53 102.31 270 bottom
R363  2.49K_1%  [RES0402_0-5]  58.26 102.31 270 bottom
R364  2.49K_1%  [RES0402_0-5]  62.22 102.24 270 bottom
R365  220E  [RES0402_0-5]  81.63 100.69 0 bottom
R366  499E_1%  [RES0402_0-5]  43.28 100.64 90 bottom
R367  5.76K_1%  [RES0402_0-5]  57.49 100.26 270 bottom
R368  2.49K_1%  [RES0402_0-5]  56.05 100.26 270 bottom
R369  10K  [RES0201_0-5]  62.95 100.23 90 bottom
R370  2.2K  [RES0201_0-5]  61.94 100.23 90 bottom
R371  22E_1%  [RES0201_0-5]  59.4 100.23 270 bottom
R372  22E_1%  [RES0201_0-5]  58.51 100.23 270 bottom
R373  220E  [RES0402_0-5]  81.63 98.61 180 bottom
R374  2.49K_1%  [RES0402_0-5]  55.1 98.16 180 bottom
R375  240E_1%  [RES0402_0-5]  36.29 96.73 270 bottom
R376  2.49K_1%  [RES0402_0-5]  55.1 96.66 180 bottom
R377  0E  [RES0402_0-5]  55.1 95.51 0 bottom
R378  11K_1%  [RES0402_0-5]  66.19 91.6 0 bottom
R379  100K  [RES0201_0-5]  2.36 85.42 180 bottom
